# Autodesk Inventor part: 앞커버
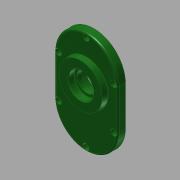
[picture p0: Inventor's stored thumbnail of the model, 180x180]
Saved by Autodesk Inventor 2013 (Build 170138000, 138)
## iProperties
Created: 2016-12
Part Number: 앞커버
Material: 일반
Document SubType Name: Modeling
Designer: mduedu
Density: 1 g/cm^3
Author: mduedu
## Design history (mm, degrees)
sketch "스케치1"
  geometry: L1 (40, -25)-(40, 25); L2 (-40, 25)-(-40, -25); L3 (-40, -25)-(40, 25); L4 (40, -25)-(-40, 25); A1 r 40 centre (0, 25) between (40, 25) and (-40, 25); A2 r 40 centre (0, -25) between (-40, -25) and (40, -25); 1 further point
  constraints: 8 end point, 4 point on circle, 4 tangent, 2 centre point, 2 midpoint, 1 parallel, 1 vertical
  dimensions: "d0" = 130 dimension on A2 A1; "d2" = 80 distance between parallel lines of L1 L2
extrude "돌출1" new body sketch "스케치1" distance "d3" = 10; taper "d4" = 0 deg
sketch "스케치2"
  geometry: C1 r 21 at (0, 11); 1 further point
  constraints: 1 centre point, 1 vertical alignment
  dimensions: "d5" = 42 diameter of C1; "d7" = 11 distance of C1.centre point (0, 0)
extrude "돌출2" join sketch "스케치2" distance "d8" = 7; taper "d9" = 0 deg
sketch "스케치3"
  geometry: C1 r 15 at (0, -33.1); C2 r 21 at (0, 11) reference; 1 further point
  constraints: 1 centre point, 1 vertical alignment
  dimensions: "d10" = 30 diameter of C1; "d71" = 44.1 distance of C1.centre C2.centre
extrude "돌출3" join sketch "스케치3" distance "d12" = 7; taper "d13" = 0 deg
sketch "스케치4"
  geometry: C1 r 28 at (0, 11); A1 r 21 centre (0, 11) between (8.978, -7.984) and (-8.978, -7.984) reference; 1 further point
  constraints: 1 centre point, 1 coincident
  dimensions: "d14" = 56 diameter of C1
extrude "돌출4" join sketch "스케치4" distance "d15" = 7; taper "d16" = -5 deg
hole "구멍1" diameter "d19" = 35; stored, may be unused: countersink angle "d23" = 90 deg, drill point angle "d25" = 0 deg; dims "d17" = 10, "d18" = 10, "d20" = 6, "d21" = 4, "d22" = 2, "d24" = 10
hole "구멍2" diameter "d28" = 22; stored, may be unused: countersink angle "d32" = 90 deg, drill point angle "d34" = 0 deg; dims "d26" = 10, "d27" = 10, "d29" = 6, "d30" = 4, "d31" = 2, "d33" = 7
hole "구멍3" diameter "d37" = 19; stored, may be unused: countersink angle "d41" = 90 deg, drill point angle "d43" = 0 deg; dims "d35" = 10, "d36" = 10, "d38" = 6, "d39" = 4, "d40" = 2, "d42" = 1
hole "구멍4" diameter "d46" = 32; stored, may be unused: countersink angle "d50" = 90 deg, drill point angle "d52" = 0 deg; dims "d44" = 10, "d45" = 10, "d47" = 6, "d48" = 4, "d49" = 2, "d51" = 8
hole "구멍5" diameter "d55" = 25; stored, may be unused: countersink angle "d59" = 90 deg, drill point angle "d61" = 0 deg; dims "d53" = 10, "d54" = 10, "d56" = 6, "d57" = 4, "d58" = 2, "d60" = 8
fillet "모깎기1" dims "d62" = 0.3
fillet "모깎기2" dims "d63" = 2
chamfer "모따기1" distance "d64" = 1; stored, may be unused: second distance "d65" = 2, angle "d66" = 45 deg
fillet "모깎기4" dims "d68" = 2
fillet "모깎기5" dims "d69" = 0.3
fillet "모깎기6" dims "d70" = 2
sketch "스케치5"
  geometry: L1 (-40, 25)-(-40, -25) reference; L2 (40, -25)-(40, 25) reference; L3 (35, 25)-(35, -25); L4 (-35, -25)-(-35, 25); A1 r 40 centre (0, 25) between (40, 25) and (-40, 25) reference; A2 r 40 centre (0, -25) between (-40, -25) and (40, -25) reference; A3 r 35 centre (0, 25) between (35, 25) and (-35, 25); A4 r 35 centre (0, -25) between (-35, -25) and (35, -25); 2 further points
  constraints: 5 point on circle, 4 end point, 2 centre point, 1 vertical alignment, 3 other
  dimensions: "d72" = 5 distance between parallel lines of L2 L3
sketch "스케치7"
  geometry: 1 further point
hole "구멍7" sketch "스케치7" at (0, 60) diameter "d80" = 4.5; stored, may be unused: countersink angle "d84" = 90 deg, drill point angle "d86" = 0 deg; dims "d81" = 6, "d82" = 8, "d83" = 4.6, "d85" = 8
node "솔리드1"
pattern_linear "직사각형 패턴1"
